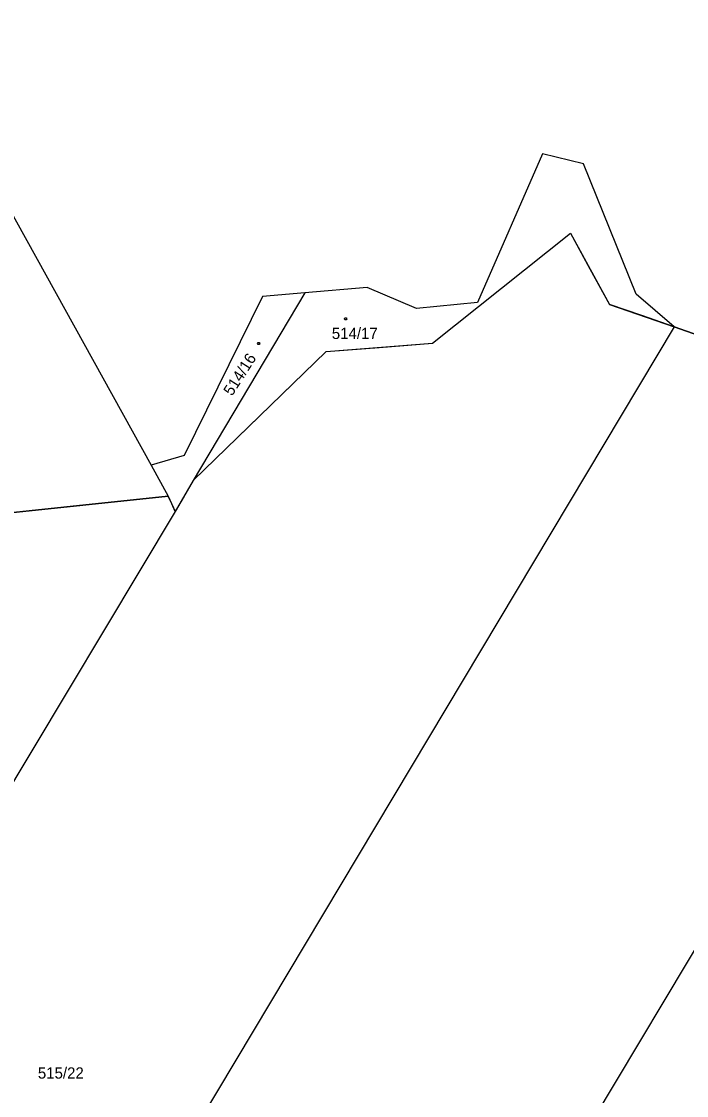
# Model space of a CAD drawing. Extents: x -634640 to -629202, y -1196156 to -1190068.
# Drawn here: x -631907.6 to -631806.9, y -1192976.1 to -1192813.6 of the extents above; entities that cross this region are included whole.
import ezdxf

# ---------------------------------------------------------------- set-up
doc = ezdxf.new("R2010")
doc.units = 0
for name, color, linetype in [('Obvod převzatý', 7, 'Continuous'), ('Obvod šetřený', 7, 'Continuous'), ('Vrstva 1', 7, 'Continuous'), ('Vrstva 2', 7, 'Continuous'), ('Vrstva 3', 7, 'Continuous')]:
    doc.layers.add(name, color=color, linetype=linetype)

msp = doc.modelspace()

# ---------------------------------------------------------------- linework, layer by layer
at = {"layer": 'Obvod převzatý'}
msp.add_lwpolyline([(-631881.59, -1192883.11), (-631871.525, -1192873.35), (-631861.46, -1192863.59), (-631853.395, -1192862.945), (-631845.33, -1192862.3), (-631834.895, -1192853.99), (-631824.46, -1192845.68), (-631821.495, -1192851.06), (-631818.53, -1192856.44)], dxfattribs=at)
at = {"layer": 'Obvod šetřený'}
for points in [[(-631804.99, -1192861.17), (-631806.875, -1192860.51), (-631808.76, -1192859.85), (-631813.645, -1192858.145), (-631818.53, -1192856.44)], [(-631881.59, -1192883.11), (-631882.955, -1192885.455), (-631884.32, -1192887.8), (-631884.83, -1192886.64), (-631885.34, -1192885.48), (-631901.16, -1192887.14), (-631916.98, -1192888.8), (-631933.245, -1192909.24), (-631949.51, -1192929.68), (-631956.32, -1192925.645), (-631963.13, -1192921.61), (-631965.445, -1192917.355), (-631967.76, -1192913.1), (-631975.3, -1192912.105), (-631982.84, -1192911.11)]]:
    msp.add_lwpolyline(points, dxfattribs=at)
at = {"layer": 'Vrstva 1'}
for p, q in [((-631925.16, -1192813.64), (-631887.96, -1192880.75)), ((-631828.68, -1192833.69), (-631838.51, -1192856.14)), ((-631822.5, -1192835.17), (-631828.68, -1192833.69)), ((-631814.5, -1192854.92), (-631822.5, -1192835.17)), ((-631845.33, -1192862.3), (-631824.46, -1192845.68)), ((-631824.46, -1192845.68), (-631818.53, -1192856.44)), ((-631869.39, -1193060.67), (-631743.31, -1192849.98)), ((-631855.22, -1192853.88), (-631864.67, -1192854.69)), ((-631847.74, -1192857.05), (-631855.22, -1192853.88)), ((-631871.09, -1192855.24), (-631882.95, -1192879.32)), ((-631864.67, -1192854.69), (-631881.59, -1192883.11)), ((-631864.67, -1192854.69), (-631871.09, -1192855.24)), ((-631808.76, -1192859.85), (-631814.5, -1192854.92)), ((-631838.51, -1192856.14), (-631847.74, -1192857.05)), ((-631818.53, -1192856.44), (-631808.76, -1192859.85)), ((-631808.76, -1192859.85), (-631924.73, -1193053.67)), ((-631808.76, -1192859.85), (-631804.99, -1192861.17)), ((-631861.46, -1192863.59), (-631881.59, -1192883.11)), ((-631861.46, -1192863.59), (-631845.33, -1192862.3)), ((-631882.95, -1192879.32), (-631887.96, -1192880.75)), ((-631887.96, -1192880.75), (-631885.34, -1192885.48)), ((-631881.59, -1192883.11), (-631884.32, -1192887.8)), ((-631916.98, -1192888.8), (-631885.34, -1192885.48)), ((-631885.34, -1192885.48), (-631884.32, -1192887.8)), ((-631884.32, -1192887.8), (-631979.58, -1193046.73))]:
    msp.add_line(p, q, dxfattribs=at)
at = {"layer": 'Vrstva 3'}
for points in [[(-631858.41, -1192858.47), (-631858.32, -1192858.62), (-631858.41, -1192858.77), (-631858.59, -1192858.77), (-631858.68, -1192858.62), (-631858.59, -1192858.47), (-631858.41, -1192858.47)], [(-631871.57, -1192862.19), (-631871.48, -1192862.34), (-631871.57, -1192862.49), (-631871.75, -1192862.49), (-631871.84, -1192862.34), (-631871.75, -1192862.19), (-631871.57, -1192862.19)]]:
    msp.add_lwpolyline(points, dxfattribs=at)

# ---------------------------------------------------------------- texts
at = {"layer": 'Vrstva 2'}
for s, p in [('514/17', (-631860.583, -1192861.68)), ('515/22', (-631905.093, -1192973.59))]:
    msp.add_text(s, height=1.7, dxfattribs=at).set_placement(p)
msp.add_text('514/16', height=1.7, rotation=57.35308, dxfattribs=at).set_placement((-631875.692, -1192870.41))

doc.saveas('drawing.dxf')
